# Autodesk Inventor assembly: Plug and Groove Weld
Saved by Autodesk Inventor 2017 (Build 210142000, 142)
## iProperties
Created: 2016-08
Part Number: Plug and Groove Weld
Document SubType Name: Assembly
Designer: Gaurav
ClientObjectVersion: 1
Author: Gaurav
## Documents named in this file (1)
- D:\My Data\Books_Final Books\Autodesk Inventor 2015_resources\Chapter 11\Practical_1\Practical_1\Design Accelerator\Plug and Groove Weld2.iam
